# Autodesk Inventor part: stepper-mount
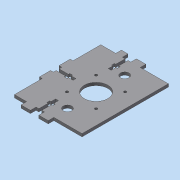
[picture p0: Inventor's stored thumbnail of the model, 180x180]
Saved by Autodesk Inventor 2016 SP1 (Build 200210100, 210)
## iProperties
Created: 2016-06
Part Number: stepper-mount
Material: Generic
Document SubType Name: Modeling
Designer: Mohamed A.
Density: 1 g/cm^3
Appearance: Default
Author: Mohamed A.
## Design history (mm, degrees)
sketch "Sketch1"
  geometry: L1 (-37.5, -49)-(37.5, -49); L2 (37.5, -49)-(37.5, 49); L3 (37.5, 49)-(-37.5, 49); L4 (-37.5, 49)-(-37.5, -49); L5 (-37.5, -49)-(37.5, 49); L6 (37.5, -49)-(-37.5, 49); 1 further point
  constraints: 12 end point, 2 midpoint, 2 parallel, 1 horizontal, 1 perpendicular
  dimensions: "d0" = 75 distance of L2.end L3.end; "d1" = 98 distance of L3.end L1.start
extrude "Extrusion1" new body sketch "Sketch1" distance "d2" = 3; taper "d3" = 0 deg
sketch "Sketch2"
  geometry: L1 (47.5, 46)-(-34.5, 46) reference; L2 (-34.5, -46)-(47.5, -46) reference; L3 (6.5, -46)-(6.5, 46); L4 (-14.5, 21)-(27.5, 21) reference; L5 (27.5, -21)-(-14.5, -21) reference; C1 r 1.5 at (22, -15.5) reference; C2 r 1.5 at (22, 15.5) reference; C3 r 1.5 at (-9, 15.5) reference; C4 r 1.5 at (-9, -15.5) reference; C5 r 12.5 at (6.5, 0) reference; C6 r 1.4 at (-9, -15.5); C7 r 1.4 at (-9, 15.5); C8 r 1.4 at (22, 15.5); C9 r 1.4 at (22, -15.5); C10 r 4.5 at (6.5, 30.5); C11 r 4.5 at (6.5, -30.5); 1 further point
  constraints: 6 centre point, 4 coincident, 3 midpoint, 2 end point, 2 point on line, 1 perpendicular
  dimensions: "d6" = 2.8 diameter of C6; "d7" = 2.8 diameter of C7; "d8" = 2.8 diameter of C8; "d9" = 2.8 diameter of C9; "d10" = 9 diameter of C10; "d13" = 9 diameter of C11; "d16" = 9.5 distance from line of L4 C10.centre (computed from d10); "d17" = 9.5 distance from line of C11.centre L5 (= d16)
extrude "Extrusion2" cut sketch "Sketch2" distance "d4" = 3; taper "d5" = 0 deg
sketch "Sketch3"
  geometry: L1 (-37.5, 49)-(-37.5, -49) reference; L2 (-37.5, 0)-(-11.464, 0); L3 (-37.5, 1.55)-(-16.5, 1.55); L4 (-16.5, 1.55)-(-16.5, -1.55); L5 (-16.5, -1.55)-(-37.5, -1.55); L6 (-37.5, -1.55)-(-37.5, 1.55); L7 (-24.5, 3)-(-21.5, 3); L8 (-21.5, 3)-(-21.5, -3); L9 (-21.5, -3)-(-24.5, -3); L10 (-24.5, -3)-(-24.5, 3); L11 (-37.5, 4.5)-(-34.5, 4.5); L12 (-34.5, 4.5)-(-34.5, -4.5); L13 (-34.5, -4.5)-(-37.5, -4.5); L14 (-37.5, -4.5)-(-37.5, 4.5); L15 (-4.005, 33)-(-10.005, 33); L16 (-10.005, 33)-(-10.005, 36); L17 (-4.005, 36)-(-4.005, 33); L18 (-10.005, 36)-(-4.005, 36); L19 (-7.005, 48.589)-(-7.005, 22.553); L20 (-5.455, 49)-(-5.455, 28); L21 (-8.555, 28)-(-8.555, 49); L22 (-11.505, 46)-(-11.505, 49); L23 (-2.505, 49)-(-2.505, 46); L24 (-2.505, 46)-(-11.505, 46); L25 (-5.455, 28)-(-8.555, 28); L26 (-11.505, 49)-(-2.505, 49); L27 (-8.555, 49)-(-5.455, 49); L28 (37.5, 49)-(-37.5, 49) reference; L29 (-10.005, -33)-(-10.005, -36); L30 (-11.505, -46)-(-11.505, -49); L31 (-8.555, -28)-(-8.555, -49); L32 (-7.005, -48.589)-(-7.005, -22.553); L33 (-5.455, -28)-(-8.555, -28); L34 (-8.555, -49)-(-5.455, -49); L35 (-5.455, -49)-(-5.455, -28); L36 (-4.005, -33)-(-10.005, -33); L37 (-4.005, -36)-(-4.005, -33); L38 (-10.005, -36)-(-4.005, -36); L39 (-2.505, -46)-(-11.505, -46); L40 (-2.505, -49)-(-2.505, -46); L41 (-11.505, -49)-(-2.505, -49); L42 (-37.5, 49)-(-34.5, 49); L43 (-34.5, 49)-(-34.5, 16.333); L44 (-34.5, 16.333)-(-37.5, 16.333); L45 (-37.5, 16.333)-(-37.5, 49); L46 (-37.5, -49)-(-34.5, -49); L47 (-34.5, -49)-(-34.5, -16.333); L48 (-34.5, -16.333)-(-37.5, -16.333); L49 (-37.5, -16.333)-(-37.5, -49); L50 (-34.5, -49)-(-21.505, -49); L51 (-21.505, -49)-(-21.505, -46); L52 (-21.505, -46)-(-34.5, -46); L53 (-34.5, -46)-(-34.5, -49); L54 (-37.5, -49)-(37.5, -49) reference; L55 (37.5, -49)-(7.495, -49); L56 (7.495, -49)-(7.495, -46); L57 (7.495, -46)-(37.5, -46); L58 (37.5, -46)-(37.5, -49); L59 (37.5, 49)-(7.495, 49); L60 (7.495, 49)-(7.495, 46); L61 (7.495, 46)-(37.5, 46); L62 (37.5, 46)-(37.5, 49); L63 (-34.5, 49)-(-18.555, 49); L64 (-18.555, 49)-(-18.555, 46)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; 1 further point
  constraints: 126 end point, 24 parallel, 14 symmetric about line, 12 perpendicular, 10 horizontal, 5 point on line, 2 collinear, 1 midpoint, 6 other
  dimensions: "d18" = 21 distance of L4.end L5.end; "d19" = 3.1 distance of L3.end L4.end; "d20" = 3 distance of L8.end L9.end; "d21" = 6 distance of L7.end L8.end; "d22" = 5 distance between parallel lines of L8 L4; "d23" = 3 distance between parallel lines of L14 L12; "d24" = 9 distance between parallel lines of L13 L11; "d25" = 21 distance of L21.start L21.end; "d26" = 3.1 distance of L20.end L21.start; "d27" = 3 distance of L15.end L16.end; "d28" = 6 distance of L15.start L15.end; "d29" = 5 distance between parallel lines of L15 L25; "d30" = 3 distance between parallel lines of L26 L24; "d31" = 9 distance between parallel lines of L22 L23; "d34" = 98 distance between parallel lines of L54 L28 (derived); "d35" = 32.66667 distance between parallel lines of L28 L44 (= 0.333333 x d34); "d36" = 32.66667 distance between parallel lines of L54 L48 (= d35); "d37" = 10 distance between parallel lines of L21 L64; "d38" = 10 distance between parallel lines of L23 L60; "d39" = 10 distance between parallel lines of L51 L30 (= d37); "d40" = 10 distance between parallel lines of L40 L56 (derived); "d45" = 3 distance between parallel lines of L28 L65; "d46" = 3 distance between parallel lines of L52 L54
extrude "Extrusion3" cut sketch "Sketch3" distance "d32" = 3; taper "d33" = 0 deg
sketch "Sketch4"
  geometry: L1 (0, 3)-(0, 0) reference; L2 (0, 0)-(10, 0) reference; L3 (10, 0)-(10, 3) reference; L4 (0, 3)-(10, 3) reference; L5 (-9, 0)-(-9, 3) reference; L6 (-19, 3)-(-9, 3) reference; L7 (-19, 3)-(-19, 0) reference; L8 (-19, 0)-(-9, 0) reference; 1 further point
extrude "Extrusion4" join sketch "Sketch4" distance "d41" = 3; taper "d42" = 0 deg
sketch "Sketch5"
  geometry: L1 (0, 0)-(0, -3) reference; L2 (7.05, -3)-(0, -3) reference; L3 (7.05, -3)-(7.05, 0) reference; L4 (7.05, 0)-(0, 0) reference; L5 (26.05, -3)-(26.05, 0) reference; L6 (26.05, 0)-(16.05, 0) reference; L7 (16.05, 0)-(16.05, -3) reference; L8 (26.05, -3)-(16.05, -3) reference; 1 further point
extrude "Extrusion5" join sketch "Sketch5" distance "d43" = 3; taper "d44" = 0 deg
body "Solid1"
node "Reference1"
node "Reference2"
node "Reference3"
node "Reference4"
node "Reference5"
node "Reference8"
node "Reference9"
node "Reference10"
node "Reference11"
node "Projected Loop1"
node "Projected Loop2"
node "Projected Loop3"
node "Projected Loop4"
